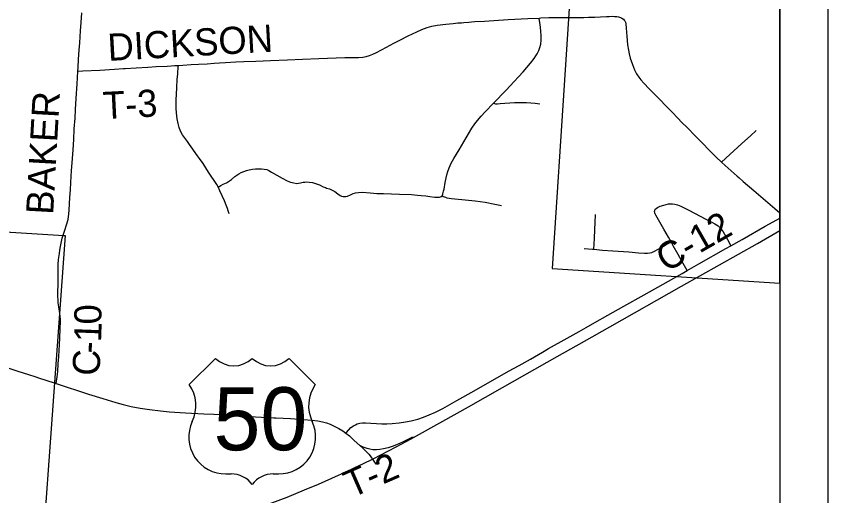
# Model space of a CAD drawing. Extents: x 0 to 34, y 0 to 22.
# Drawn here: x 7.302 to 9, y 15.949 to 16.952 of the extents above; entities that cross this region are included whole.
import ezdxf

# ---------------------------------------------------------------- set-up
doc = ezdxf.new("R2010")
doc.units = 0
for name, color, linetype in [('GM_X_Corporation', 7, 'Continuous'), ('GM_X_County_Road', 7, 'Continuous'), ('GM_X_County_Road_Text', 7, 'Continuous'), ('GM_X_Interchange_Ramps', 7, 'Continuous'), ('GM_X_State_Route', 7, 'Continuous'), ('GM_X_Township_Road', 7, 'Continuous'), ('GM_X_Township_Road_Text', 7, 'Continuous'), ('GM_X_US_Location', 7, 'Continuous'), ('GM_X_US_Route', 7, 'Continuous'), ('GM_X_US_Shield', 7, 'Continuous'), ('SH_Data', 7, 'Continuous')]:
    doc.layers.add(name, color=color, linetype=linetype)

msp = doc.modelspace()

# ---------------------------------------------------------------- linework, layer by layer
at = {"layer": 'GM_X_Corporation'}
for points in [[(8.9, 16.3939), (8.9, 17.4412), (8.4898, 17.4646), (8.4777, 17.2575), (8.4507, 16.8404), (8.4238, 16.4246)], [(6.3752, 16.5579), (7.4018, 16.494), (7.4044, 16.4938), (7.3299, 15.4642), (6.2993, 15.5265)]]:
    msp.add_lwpolyline(points, close=True, dxfattribs=at)
at = {"layer": 'GM_X_County_Road'}
for points in [[(7.3859, 16.1842), (7.3865, 16.1887), (7.3879, 16.1982), (7.3891, 16.2091), (7.3904, 16.2255), (7.3912, 16.2404), (7.3926, 16.2658), (7.3934, 16.2789), (7.3946, 16.2993), (7.3949, 16.3131), (7.3948, 16.3177), (7.3944, 16.3244), (7.3937, 16.3303), (7.3913, 16.3443), (7.3902, 16.3528), (7.3898, 16.3586), (7.3897, 16.3668), (7.3902, 16.3998), (7.3901, 16.4332), (7.3909, 16.4435), (7.3926, 16.4559), (7.3936, 16.4632), (7.3948, 16.4707), (7.397, 16.4815), (7.3987, 16.4884), (7.4034, 16.5027), (7.4085, 16.5178), (7.4109, 16.5273), (7.4122, 16.5392), (7.4129, 16.5469), (7.4147, 16.5729), (7.4157, 16.5889), (7.4165, 16.6045), (7.4182, 16.6298), (7.4193, 16.6457), (7.4214, 16.6727), (7.4226, 16.6944), (7.4237, 16.7166), (7.4253, 16.7392), (7.4265, 16.757), (7.4278, 16.7802), (7.4297, 16.811), (7.4305, 16.8236), (7.4314, 16.8374), (7.4318, 16.8449), (7.4328, 16.8624), (7.4341, 16.8813), (7.4352, 16.8966), (7.4371, 16.9217), (7.438, 16.939), (7.4394, 16.9594)], [(8.0885, 16.1005), (8.1034, 16.1018), (8.1164, 16.1036), (8.1286, 16.106), (8.1425, 16.1096), (8.1543, 16.1135), (8.1665, 16.1183), (8.1796, 16.1242), (8.1945, 16.1319), (8.2243, 16.1487), (8.26, 16.1688), (8.3324, 16.2098), (8.3541, 16.2219), (8.3779, 16.2353), (8.4031, 16.25), (8.4161, 16.2572), (8.4547, 16.2786), (8.4801, 16.293), (8.4946, 16.3014), (8.5129, 16.312), (8.5401, 16.3269), (8.5736, 16.3459), (8.6157, 16.3697), (8.6666, 16.3984), (8.6953, 16.4144), (8.7056, 16.4203), (8.7304, 16.4344), (8.7866, 16.4662), (8.7975, 16.4723), (8.8207, 16.4854), (8.8693, 16.5131), (8.8936, 16.5266), (8.9, 16.5302)], [(7.9921, 16.0802), (7.9934, 16.0816), (8.0026, 16.092), (8.0081, 16.0958), (8.0118, 16.0979), (8.0158, 16.0995), (8.021, 16.1009), (8.0264, 16.1016), (8.0332, 16.1018), (8.0673, 16.1), (8.0773, 16.0999), (8.0885, 16.1005)]]:
    msp.add_lwpolyline(points, dxfattribs=at)
at = {"layer": 'GM_X_Interchange_Ramps'}
msp.add_lwpolyline([(8.1337, 16.0712), (8.1316, 16.0711), (8.1302, 16.0709), (8.1288, 16.0705), (8.1274, 16.0699), (8.1242, 16.0683), (8.1107, 16.0615), (8.0977, 16.056), (8.0891, 16.0526), (8.0803, 16.0497), (8.0706, 16.0474), (8.0627, 16.0461), (8.0559, 16.0456), (8.0484, 16.0457), (8.0423, 16.0465), (8.0362, 16.048), (8.0278, 16.0512), (8.0213, 16.0544)], dxfattribs=at)
at = {"layer": 'GM_X_State_Route'}
for points in [[(8.0093, 16.0076), (8.029, 16.017), (8.0473, 16.026)], [(7.2917, 15.7539), (7.3441, 15.7709), (7.3883, 15.7856), (7.4441, 15.8038), (7.5008, 15.8223), (7.5616, 15.8421), (7.6557, 15.8731), (7.714, 15.8919), (7.7468, 15.9025), (7.8086, 15.9238), (7.8367, 15.9343), (7.8688, 15.9466), (7.9053, 15.9614), (7.935, 15.9738), (7.9627, 15.986), (7.9967, 16.0017), (8.0093, 16.0076)]]:
    msp.add_lwpolyline(points, dxfattribs=at)
at = {"layer": 'GM_X_Township_Road'}
for points in [[(7.4314, 16.8374), (7.4415, 16.8379), (7.4769, 16.8396), (7.5079, 16.8416), (7.5264, 16.8428), (7.53, 16.843), (7.5531, 16.8444), (7.5773, 16.846), (7.5953, 16.847), (7.6182, 16.8482), (7.6262, 16.8486), (7.6337, 16.8491), (7.6415, 16.8496), (7.651, 16.8502), (7.6684, 16.8513), (7.6839, 16.852), (7.7018, 16.8531), (7.7161, 16.8541), (7.7278, 16.8548), (7.7402, 16.8555), (7.7618, 16.8567), (7.7785, 16.8574), (7.8039, 16.8585), (7.8343, 16.86), (7.8696, 16.8614), (7.9012, 16.8627), (7.9353, 16.864), (7.9898, 16.8658), (8.0184, 16.8663), (8.0272, 16.867), (8.0346, 16.8683), (8.0413, 16.8702), (8.0483, 16.8728), (8.0563, 16.8765), (8.077, 16.8878), (8.0924, 16.8959), (8.1051, 16.9025), (8.1222, 16.9112), (8.1401, 16.9198), (8.1509, 16.9245), (8.1618, 16.9286), (8.1719, 16.9315), (8.1828, 16.9334), (8.2007, 16.9355), (8.2087, 16.9363), (8.2161, 16.9373), (8.226, 16.9383), (8.234, 16.9388), (8.2389, 16.9393), (8.2488, 16.9401), (8.255, 16.9407), (8.2618, 16.9412), (8.2816, 16.9424), (8.3014, 16.9437), (8.3312, 16.9455), (8.3728, 16.9473), (8.3963, 16.9486), (8.4001, 16.9488), (8.4168, 16.9494), (8.4372, 16.9497), (8.4632, 16.9496), (8.4769, 16.9496), (8.4899, 16.9499), (8.4992, 16.9501), (8.5033, 16.9503), (8.5128, 16.9507), (8.5246, 16.9513), (8.537, 16.9519), (8.5425, 16.9521), (8.5487, 16.9523), (8.5536, 16.9521), (8.5585, 16.9517), (8.5623, 16.951), (8.5661, 16.9496), (8.5694, 16.948), (8.5724, 16.9463), (8.5742, 16.9445), (8.5758, 16.9425), (8.5771, 16.9403), (8.5778, 16.9362), (8.5785, 16.9271), (8.5796, 16.911), (8.5813, 16.8925), (8.5829, 16.8813), (8.5844, 16.874), (8.5869, 16.8644), (8.5912, 16.8513), (8.5957, 16.8403), (8.6001, 16.832), (8.6045, 16.8252), (8.6091, 16.8192), (8.6153, 16.8122), (8.6265, 16.8005), (8.6509, 16.7758), (8.659, 16.7673), (8.6672, 16.7588), (8.6749, 16.7507), (8.6855, 16.7398), (8.6956, 16.7293), (8.7049, 16.7201), (8.7243, 16.7009), (8.7327, 16.6926), (8.7577, 16.6668), (8.7668, 16.6573), (8.7775, 16.6473), (8.7856, 16.64), (8.8107, 16.618), (8.8142, 16.6149), (8.8233, 16.607), (8.8455, 16.588), (8.889, 16.5505), (8.9, 16.5408)], [(7.7245, 16.5954), (7.7268, 16.5964), (7.7304, 16.5981), (7.7354, 16.6008), (7.742, 16.6041), (7.7464, 16.6068), (7.7525, 16.611), (7.7599, 16.6172), (7.764, 16.62), (7.7683, 16.6225), (7.7732, 16.6252), (7.7783, 16.6275), (7.7841, 16.6295), (7.7894, 16.6311), (7.7967, 16.6323), (7.8029, 16.633), (7.8089, 16.6335), (7.8155, 16.6333), (7.8212, 16.6328), (7.8267, 16.6315), (7.8311, 16.6294), (7.8365, 16.6265), (7.8589, 16.6139), (7.8694, 16.6084), (7.8763, 16.6055), (7.8829, 16.6037), (7.8892, 16.6028), (7.8931, 16.6031), (7.8973, 16.6038), (7.9029, 16.6052), (7.9061, 16.6055), (7.9104, 16.6057), (7.9152, 16.6055), (7.9219, 16.6043), (7.9307, 16.6018), (7.9367, 16.5995), (7.9447, 16.5956), (7.9493, 16.5938), (7.9516, 16.5929), (7.9575, 16.591), (7.9633, 16.5888), (7.9688, 16.5858), (7.9751, 16.5808), (7.9797, 16.5775), (7.983, 16.5759), (7.986, 16.5751), (7.989, 16.575), (7.9921, 16.5753), (7.9951, 16.5762), (8.0013, 16.579), (8.007, 16.5816), (8.0123, 16.5832), (8.0184, 16.584), (8.0265, 16.5841), (8.0428, 16.5827), (8.0569, 16.5818), (8.0704, 16.5813), (8.104, 16.58), (8.1295, 16.5792), (8.1418, 16.5784), (8.1493, 16.5777), (8.1591, 16.5764), (8.1677, 16.5752), (8.1781, 16.5742), (8.1839, 16.574), (8.1877, 16.5742), (8.1898, 16.5746), (8.191, 16.5751), (8.1934, 16.5768), (8.1945, 16.5786), (8.1951, 16.5808), (8.1963, 16.5864), (8.1972, 16.5905), (8.1997, 16.6046), (8.2031, 16.6204), (8.205, 16.6276), (8.2077, 16.6352), (8.2121, 16.6448), (8.2179, 16.6551), (8.2288, 16.6732), (8.2436, 16.6977), (8.2557, 16.7179), (8.262, 16.7272), (8.2672, 16.7341), (8.2752, 16.7436), (8.2835, 16.7527), (8.3009, 16.7702), (8.327, 16.7976), (8.344, 16.8159), (8.3532, 16.8257), (8.3628, 16.8364), (8.3779, 16.8539), (8.3858, 16.8639), (8.3895, 16.8692), (8.3924, 16.8739), (8.3957, 16.8805), (8.398, 16.887), (8.3997, 16.8942), (8.4005, 16.9022), (8.4007, 16.9109), (8.4, 16.9215), (8.3984, 16.935), (8.3966, 16.9466), (8.3963, 16.9486)], [(7.7477, 16.5388), (7.7458, 16.5452), (7.744, 16.5505), (7.7415, 16.5575), (7.7378, 16.5661), (7.7286, 16.5871), (7.7245, 16.5954), (7.7217, 16.6003), (7.7048, 16.6264), (7.6933, 16.644), (7.6857, 16.6546), (7.6814, 16.6607), (7.6681, 16.6794), (7.6649, 16.684), (7.6603, 16.6906), (7.6505, 16.7042), (7.6463, 16.7118), (7.6431, 16.7198), (7.6409, 16.7282), (7.6392, 16.7379), (7.6376, 16.7501), (7.6369, 16.7594), (7.6367, 16.7675), (7.6372, 16.778), (7.6377, 16.7885), (7.6385, 16.8034), (7.6393, 16.8202), (7.6401, 16.8319), (7.6413, 16.8473), (7.6415, 16.8496)], [(8.3009, 16.7702), (8.3048, 16.7693), (8.3093, 16.7691), (8.3149, 16.7695), (8.3447, 16.7716), (8.354, 16.772), (8.3695, 16.7716), (8.3876, 16.7703), (8.3975, 16.7693)], [(8.7775, 16.6473), (8.7953, 16.6632), (8.8199, 16.6859), (8.8381, 16.7022), (8.8505, 16.7136)], [(8.1934, 16.5768), (8.1957, 16.5755), (8.198, 16.5743), (8.2001, 16.5736), (8.2029, 16.5728), (8.213, 16.5711), (8.2417, 16.5685), (8.2627, 16.566), (8.283, 16.5631), (8.3038, 16.5591), (8.3174, 16.5566)], [(8.7056, 16.4203), (8.6976, 16.4351), (8.6871, 16.4538), (8.6766, 16.4723), (8.6722, 16.4804), (8.6667, 16.4905), (8.6571, 16.507), (8.6461, 16.5267), (8.6406, 16.5363), (8.639, 16.5391), (8.6384, 16.5412), (8.6378, 16.544), (8.6382, 16.5459), (8.6392, 16.5486), (8.6408, 16.5503), (8.644, 16.5525), (8.6495, 16.555), (8.6571, 16.5575), (8.6667, 16.5597), (8.6715, 16.5603), (8.675, 16.5602), (8.6804, 16.5591), (8.6857, 16.5576), (8.6925, 16.5548), (8.7092, 16.5466), (8.745, 16.5278), (8.7561, 16.5224), (8.764, 16.5182), (8.7705, 16.5142), (8.7737, 16.5113), (8.7772, 16.5072), (8.7813, 16.5011), (8.7899, 16.4856), (8.7975, 16.4723)], [(8.5109, 16.4649), (8.512, 16.4875), (8.5128, 16.5061), (8.5133, 16.5211), (8.5141, 16.5377)], [(8.4905, 16.4667), (8.5075, 16.4652), (8.5109, 16.4649), (8.5285, 16.4632), (8.5501, 16.4617), (8.5835, 16.4592), (8.6039, 16.4577), (8.6163, 16.4568), (8.6231, 16.4569), (8.6276, 16.4573), (8.6317, 16.4581), (8.6362, 16.4599), (8.6468, 16.4657), (8.6602, 16.4736), (8.6722, 16.4804)]]:
    msp.add_lwpolyline(points, dxfattribs=at)
at = {"layer": 'GM_X_US_Route'}
for points in [[(8.0473, 16.026), (8.0488, 16.0268), (8.0968, 16.0513), (8.1286, 16.0683), (8.1337, 16.0712), (8.1946, 16.1054), (8.2482, 16.1356), (8.3196, 16.1759), (8.4337, 16.2405), (8.491, 16.2729), (8.544, 16.3028), (8.6939, 16.3874), (8.8528, 16.4773), (8.9, 16.504)], [(7.2652, 16.2231), (7.3054, 16.21), (7.3278, 16.2028), (7.3414, 16.1985), (7.3509, 16.1955), (7.3621, 16.1919), (7.3859, 16.1842), (7.4537, 16.162), (7.4838, 16.1524), (7.5105, 16.1443), (7.526, 16.1401), (7.5429, 16.1362), (7.5618, 16.1327), (7.5814, 16.1296), (7.6041, 16.1268), (7.6233, 16.1251), (7.6561, 16.1231), (7.6946, 16.1209), (7.7157, 16.1198), (7.7392, 16.1185), (7.7621, 16.1169), (7.803, 16.1147), (7.8414, 16.1126), (7.8454, 16.1124)], [(7.8454, 16.1124), (7.8761, 16.1106), (7.904, 16.1091), (7.9202, 16.1077), (7.9331, 16.1059), (7.943, 16.104), (7.9514, 16.1017), (7.9591, 16.0989), (7.9676, 16.095), (7.977, 16.09), (7.9855, 16.0848), (7.9921, 16.0802), (7.9995, 16.0743), (8.0096, 16.0651), (8.0213, 16.0544), (8.0271, 16.0488), (8.0398, 16.0361), (8.0426, 16.0328), (8.0455, 16.0287), (8.0473, 16.026), (8.0501, 16.0218), (8.0543, 16.0157)]]:
    msp.add_lwpolyline(points, dxfattribs=at)
at = {"layer": 'GM_X_US_Shield'}
for p, q in [((7.7191, 16.2367), (7.6642, 16.1818)), ((7.9279, 16.1818), (7.873, 16.2367)), ((7.7411, 15.995), (7.7521, 15.995)), ((7.84, 15.995), (7.851, 15.995))]:
    msp.add_line(p, q, dxfattribs=at)
for centre, radius, start, end in [((7.7576, 16.2759), 0.0549, 225.573, 314.427), ((7.8345, 16.2759), 0.0549, 225.573, 314.427), ((7.6012, 16.1376), 0.0769, 334.5471, 35.0009), ((7.9909, 16.1376), 0.0769, 144.9991, 205.4529), ((7.7403, 16.0719), 0.0769, 154.8319, 270.6383), ((7.8518, 16.0719), 0.0769, 269.3617, 25.1681), ((7.7521, 15.9401), 0.0549, 36.8699, 90), ((7.84, 15.9401), 0.0549, 90, 143.1301)]:
    msp.add_arc(centre, radius, start, end, dxfattribs=at)
at = {"layer": 'SH_Data'}
for p, q in [((9, 21), (9, 14)), ((8.9, 20.9), (8.9, 14.1))]:
    msp.add_line(p, q, dxfattribs=at)

# ---------------------------------------------------------------- texts
at = {"layer": 'GM_X_County_Road_Text'}
for s, height, rotation, p in [('BAKER', 0.05682, 86.7968, (7.3795, 16.5363)), ('C-12', 0.05682, 29.7441, (8.6617, 16.4156)), ('0', 0.0568, 90.9505, (7.481, 16.3081)), ('1', 0.0568, 87.8678, (7.4797, 16.2698)), ('-', 0.0568, 87.3729, (7.4786, 16.246)), ('C', 0.0568, 87.2473, (7.4763, 16.1992))]:
    msp.add_text(s, height=height, rotation=rotation, dxfattribs=at).set_placement(p)
at = {"layer": 'GM_X_Township_Road_Text'}
for s, rotation, p in [('DICKSON', 3.2393, (7.495, 16.8588)), ('T-3', 2.8627, (7.4851, 16.7372)), ('T-2', 23.572, (8.0037, 15.944))]:
    msp.add_text(s, height=0.05682, rotation=rotation, dxfattribs=at).set_placement(p)
at = {"layer": 'GM_X_US_Location'}
for s in ['0', '/']:
    msp.add_text(s, height=0.000189, dxfattribs=at).set_placement((7.796, 16.1093))
msp.add_text('50', height=0.000189, rotation=0, dxfattribs=at).set_placement((7.7569, 16.0701))
at = {"layer": 'GM_X_US_Shield'}
msp.add_text('50', height=0.13184, dxfattribs=at).set_placement((7.7151, 16.0444))

doc.saveas('drawing.dxf')
